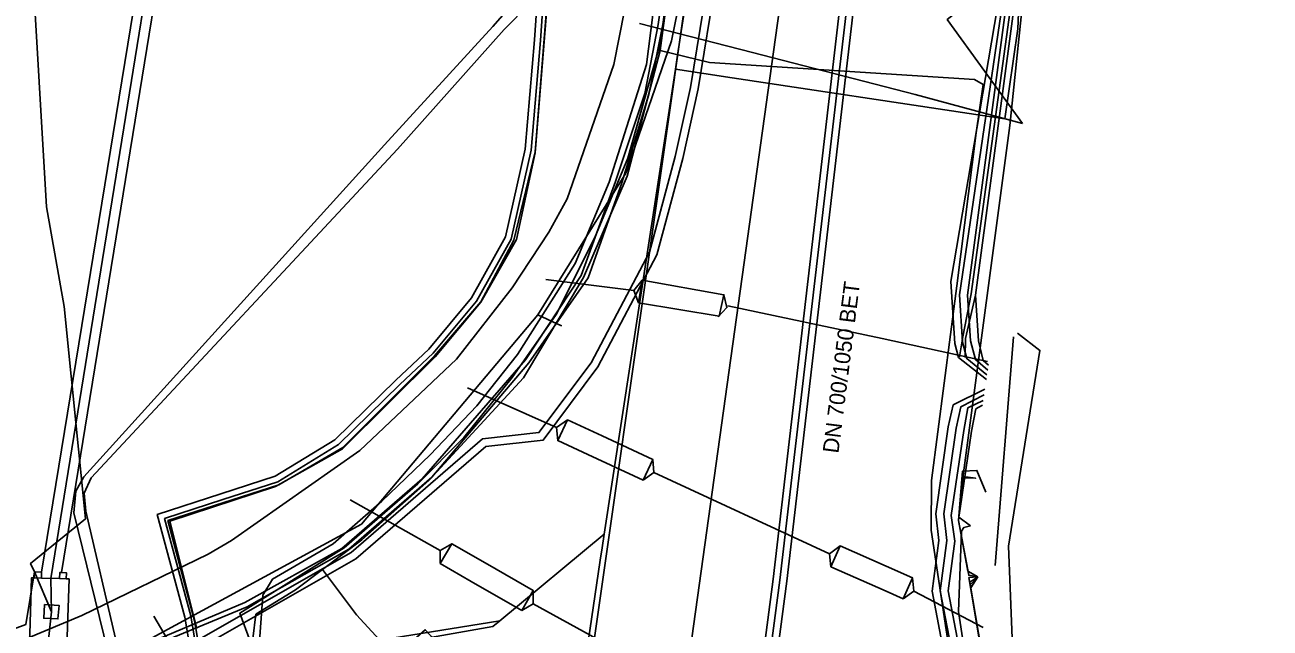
# Model space of a CAD drawing. Extents: x -600309 to -598967, y -1161267 to -1160292.
# Drawn here: x -599138.8 to -599076.1, y -1161098.5 to -1161068.1 of the extents above; entities that cross this region are included whole.
import ezdxf

# ---------------------------------------------------------------- set-up
doc = ezdxf.new("R2010")
doc.units = 0
for name, color, linetype in [('Vrstva 10', 7, 'Continuous'), ('Vrstva 12', 7, 'Continuous'), ('Vrstva 13', 7, 'Continuous'), ('Vrstva 16', 7, 'Continuous'), ('Vrstva 19', 7, 'Continuous'), ('Vrstva 32', 7, 'Continuous'), ('Vrstva 42', 7, 'Continuous'), ('Vrstva 43', 7, 'Continuous'), ('Vrstva 44', 7, 'Continuous'), ('Vrstva 54', 7, 'Continuous'), ('Vrstva 55', 7, 'Continuous'), ('Vrstva 58', 7, 'Continuous'), ('Vrstva 9', 7, 'Continuous')]:
    doc.layers.add(name, color=color, linetype=linetype)

msp = doc.modelspace()

# ---------------------------------------------------------------- linework, layer by layer
at = {"layer": 'Vrstva 10'}
for points in [[(-599137.95, -1161095.67), (-599128.84, -1161039.95)], [(-599136.95, -1161095.7), (-599127.87, -1161039.94)], [(-599100.307, -1161113.292), (-599101.123, -1161110.328), (-599101.597, -1161108.582), (-599101.858, -1161106.427), (-599101.913, -1161103.076), (-599101.585, -1161099.356), (-599101.15, -1161096.037), (-599096.816, -1161058.866)], [(-599096.12, -1161058.948), (-599100.456, -1161096.123), (-599100.889, -1161099.432), (-599101.213, -1161103.101), (-599101.159, -1161106.379), (-599100.908, -1161108.447), (-599100.448, -1161110.144), (-599099.632, -1161113.107)], [(-599138.32, -1161095.96), (-599138.31, -1161095.66), (-599137.95, -1161095.67)], [(-599137.96, -1161095.98), (-599137.95, -1161095.67)], [(-599136.95, -1161095.7), (-599137.04, -1161095.7), (-599137.05, -1161096)], [(-599136.95, -1161095.7), (-599136.7, -1161095.71), (-599136.71, -1161096.01)], [(-599138.32, -1161095.96), (-599138.45, -1161095.96), (-599138.56, -1161099.36), (-599138.4, -1161099.36)], [(-599138.32, -1161095.96), (-599137.96, -1161095.98)], [(-599137.96, -1161095.98), (-599137.05, -1161096)], [(-599137.05, -1161096), (-599136.71, -1161096.01)], [(-599136.71, -1161096.01), (-599136.57, -1161096.02), (-599136.68, -1161099.42), (-599136.83, -1161099.42)], [(-599137.8, -1161097.31), (-599137.07, -1161097.35), (-599137.13, -1161098.03), (-599137.84, -1161098), (-599137.8, -1161097.31)]]:
    msp.add_lwpolyline(points, dxfattribs=at)
at = {"layer": 'Vrstva 12'}
for points in [[(-599137.45, -1161097.68), (-599137.49, -1161095.99), (-599128.41, -1161039.95), (-599127.79, -1161037.74)], [(-599138.17, -1161054.32), (-599138.44, -1161064.71), (-599137.7, -1161077.29), (-599136.81, -1161082.31), (-599135.74, -1161093), (-599138.5, -1161095.24), (-599138.31, -1161095.66)], [(-599089.15, -1161062.53), (-599088.62, -1161063.21), (-599088.83, -1161068.33), (-599089.49, -1161072.87), (-599090.95, -1161072.65), (-599103.21, -1161070.8), (-599106.06, -1161070.37)], [(-599105.24, -1161064.99), (-599105.95, -1161069.66)], [(-599105.95, -1161069.66), (-599106.06, -1161070.37)], [(-599109.65, -1161093.76), (-599106.06, -1161070.37)], [(-599114.89, -1161098.12), (-599109.65, -1161093.76)], [(-599109.75, -1161094.45), (-599109.65, -1161093.76)], [(-599227.66, -1161133.37), (-599206.63, -1161129.68), (-599181.74, -1161125.58), (-599138.25, -1161117.9), (-599112.62, -1161113.97), (-599111.89, -1161109), (-599109.84, -1161095.07), (-599109.75, -1161094.45)], [(-599138.31, -1161095.66), (-599138.74, -1161098.31), (-599144.01, -1161100.25), (-599145.95, -1161101.42), (-599150.35, -1161102.7), (-599150.1, -1161106.59), (-599157.43, -1161107.74), (-599158.7, -1161105.89), (-599162.64, -1161105.89), (-599172.75, -1161107.4), (-599213.54, -1161113.75)], [(-599138.31, -1161095.66), (-599137.45, -1161097.68)], [(-599142.33, -1161117.89), (-599142.31, -1161116.76), (-599137.63, -1161099.39), (-599137.45, -1161097.68)], [(-599134.25, -1161101.76), (-599115.25, -1161098.41), (-599114.89, -1161098.12)], [(-599114.89, -1161098.12), (-599134.06, -1161101.21), (-599134.25, -1161101.76)]]:
    msp.add_lwpolyline(points, dxfattribs=at)
at = {"layer": 'Vrstva 13'}
msp.add_line((-599099.419, -1161057.267), (-599105.229, -1161099.001), dxfattribs=at)
msp.add_lwpolyline([(-599087.218, -1160924.142), (-599087.278, -1160924.842), (-599087.456, -1160926.459), (-599092.039, -1160965.733), (-599102.206, -1161043.368), (-599112.605, -1161116.263), (-599117.926, -1161169.4), (-599117.996, -1161169.89), (-599183.336, -1161201.145), (-599207.239, -1161215.957)], dxfattribs=at)
at = {"layer": 'Vrstva 16'}
for points in [[(-599090.42, -1160990.49), (-599091.72, -1161002.69), (-599092.14, -1161006.66), (-599093.39, -1161018.52), (-599093.73, -1161021.8), (-599093.9, -1161023.39), (-599094.03, -1161024.6), (-599094.38, -1161027.7), (-599097.78, -1161048.16), (-599098.24, -1161050.69), (-599100.21, -1161052.91), (-599108.15, -1161061.44), (-599108.37, -1161061.66), (-599114.17, -1161067.87), (-599114.67, -1161068.37)], [(-599114.67, -1161068.37), (-599120.05, -1161074.39), (-599135.46, -1161090.93), (-599135.8, -1161091.71), (-599135.72, -1161092.6), (-599132.74, -1161105.42), (-599142.28, -1161107.34), (-599150.28, -1161108.75), (-599151.51, -1161109.02), (-599151.83, -1161109.08)]]:
    msp.add_lwpolyline(points, dxfattribs=at)
at = {"layer": 'Vrstva 19'}
for points in [[(-599090.16, -1160981.76), (-599090.66, -1160985.81), (-599091.1, -1160989.88), (-599092.32, -1161001.99), (-599094.19, -1161018.43), (-599094.55, -1161021.61), (-599094.9, -1161024.69), (-599095.21, -1161027.65), (-599098.94, -1161050.34), (-599100.64, -1161052.4), (-599108.52, -1161060.96), (-599114.487, -1161067.355), (-599114.51, -1161067.38), (-599115.24, -1161068.21)], [(-599151.98, -1161108.37), (-599150.36, -1161108.07), (-599146.59, -1161107.5), (-599145.81, -1161107.39), (-599145.43, -1161107.34), (-599142.35, -1161106.87), (-599133.31, -1161105), (-599136.32, -1161092.69), (-599136.23, -1161091.6), (-599135.82, -1161090.88), (-599120.7, -1161074.17), (-599115.24, -1161068.21)]]:
    msp.add_lwpolyline(points, dxfattribs=at)
at = {"layer": 'Vrstva 32'}
msp.add_lwpolyline([(-599127.13, -1161101.25), (-599126.82, -1161096.84), (-599126.34, -1161096.03), (-599123.28, -1161094.25), (-599120.83, -1161092.11), (-599118.4, -1161089.77), (-599116.06, -1161087.31), (-599114.01, -1161084.73), (-599111.11, -1161080.14), (-599109.4, -1161076.05), (-599107.52, -1161070.13), (-599106.87, -1161065.12), (-599106.14, -1161059.09), (-599105.65, -1161058.19), (-599105.52, -1161057.55), (-599104.15, -1161041), (-599104.32, -1161040.43), (-599104.66, -1161039.59), (-599104.74, -1161039.22)], dxfattribs=at)
at = {"layer": 'Vrstva 42'}
msp.add_line((-599123.82, -1161095.544), (-599122.104, -1161097.819), dxfattribs=at)
for points in [[(-599130.144, -1161098.519), (-599130.325, -1161097.797), (-599131.498, -1161093.104), (-599126.174, -1161091.36), (-599122.805, -1161089.465), (-599118.142, -1161084.833), (-599115.856, -1161082.095), (-599114.052, -1161078.937), (-599113.119, -1161074.575), (-599111.254, -1161051.565), (-599110.532, -1161042.661), (-599110.442, -1161037.878), (-599106.953, -1161037.818), (-599100.004, -1161038.299), (-599100.095, -1161032.103), (-599098.651, -1161024.824), (-599097.718, -1161019.921), (-599095.763, -1161007.197)], [(-599100.414, -1161014.387), (-599099.84, -1161014.46), (-599099.73, -1161014.71), (-599100.25, -1161018.35), (-599101.12, -1161026), (-599102.04, -1161032.9), (-599102.92, -1161039.17), (-599103.67, -1161045.42), (-599104.83, -1161053.79), (-599105.874, -1161060.666), (-599106.93, -1161068.11), (-599107.596, -1161071.592), (-599109.08, -1161076.02), (-599110.81, -1161080.75), (-599113.61, -1161084.99), (-599118.81, -1161090.98), (-599122.841, -1161094.49), (-599127.72, -1161097.21), (-599133.25, -1161099.536)], [(-599099.36, -1161013.98), (-599099.393, -1161014.316), (-599099.44, -1161014.8), (-599099.86, -1161018.38), (-599100.88, -1161026.05), (-599101.72, -1161032.93), (-599102.52, -1161039.2), (-599103.38, -1161045.47), (-599104.57, -1161053.82), (-599105.675, -1161060.689), (-599106.69, -1161068.12), (-599107.401, -1161071.642), (-599108.76, -1161076.09), (-599110.45, -1161080.87), (-599113.43, -1161085.14), (-599118.314, -1161090.903), (-599122.494, -1161094.522), (-599127.61, -1161097.43), (-599133.24, -1161099.76)], [(-599130.504, -1161099.33), (-599122.378, -1161094.686), (-599115.768, -1161088.963), (-599112.93, -1161088.652), (-599110.299, -1161085.136), (-599107.371, -1161079.566), (-599106.078, -1161074.758), (-599105.303, -1161071.281), (-599103.531, -1161060.413), (-599102.904, -1161055.233), (-599102.162, -1161048.225), (-599100.926, -1161036.764), (-599100.215, -1161024.999), (-599098.951, -1161019.44), (-599097.017, -1161019.255), (-599084.644, -1161021.242), (-599084.154, -1161021.663), (-599084.081, -1161023.764), (-599084.813, -1161031.922), (-599085.213, -1161036.217), (-599082.49, -1161040.222), (-599078.397, -1161042.629), (-599073.394, -1161041.98)], [(-599130.35, -1161099.703), (-599122.146, -1161095.014), (-599115.6, -1161089.347), (-599112.714, -1161089.031), (-599109.96, -1161085.35), (-599106.996, -1161079.713), (-599105.689, -1161074.853), (-599104.91, -1161071.357), (-599103.135, -1161060.469), (-599102.507, -1161055.278), (-599101.764, -1161048.268), (-599100.527, -1161036.798), (-599099.818, -1161025.056), (-599098.625, -1161019.811), (-599097.03, -1161019.658), (-599084.819, -1161021.619), (-599084.548, -1161021.852), (-599084.482, -1161023.753), (-599085.211, -1161031.886), (-599085.631, -1161036.373), (-599082.813, -1161040.518), (-599078.533, -1161043.05), (-599073.334, -1161042.375)], [(-599090.347, -1161085.515), (-599090.969, -1161084.981), (-599091.213, -1161084.04), (-599091.358, -1161081.729), (-599089.33, -1161066.488), (-599088.744, -1161064.124), (-599085.641, -1161060.959), (-599083.728, -1161060.585), (-599082.593, -1161060.363), (-599082.435, -1161060.333), (-599072.307, -1161058.395), (-599069.64, -1161057.526), (-599069.353, -1161057.433)], [(-599090.308, -1161085.252), (-599090.578, -1161085.018), (-599090.813, -1161084.03), (-599090.956, -1161081.743), (-599088.936, -1161066.563), (-599088.382, -1161064.326), (-599085.442, -1161061.328), (-599082.517, -1161060.756), (-599080.995, -1161060.465), (-599079.644, -1161060.206), (-599072.217, -1161058.785), (-599069.607, -1161057.932), (-599069.293, -1161057.829), (-599069.283, -1161057.826)], [(-599105.36, -1161058.37), (-599106.82, -1161069.43), (-599108.49, -1161075.75), (-599110.68, -1161080.85), (-599113.7, -1161085.89), (-599118.47, -1161091.07), (-599121.84, -1161094.05), (-599123.82, -1161095.544), (-599125.18, -1161096.57), (-599127.17, -1161097.8), (-599127.47, -1161100.28)], [(-599070.03, -1161058.7), (-599077.3, -1161060.1), (-599079.644, -1161060.206), (-599082.435, -1161060.333), (-599085.152, -1161060.456), (-599085.84, -1161060.59), (-599089.106, -1161063.922), (-599089.724, -1161066.413), (-599092.202, -1161081.051)], [(-599069.98, -1161058.99), (-599077.25, -1161060.3), (-599080.995, -1161060.465), (-599083.728, -1161060.585), (-599085.071, -1161060.644), (-599085.74, -1161060.775), (-599088.925, -1161064.023), (-599089.527, -1161066.451), (-599091.76, -1161081.715)], [(-599112.78, -1161063.518), (-599113.15, -1161068.888), (-599113.619, -1161074.387), (-599114.602, -1161078.806), (-599116.314, -1161081.875), (-599118.469, -1161084.447), (-599120.134, -1161086.022), (-599123.203, -1161089.021), (-599126.193, -1161090.853), (-599128.926, -1161091.737), (-599132.128, -1161092.782), (-599130.737, -1161097.942), (-599130.056, -1161102.037)], [(-599112.78, -1161063.518), (-599113.15, -1161068.888), (-599113.619, -1161074.387), (-599114.602, -1161078.806), (-599116.314, -1161081.875), (-599118.469, -1161084.447), (-599120.134, -1161086.022), (-599123.203, -1161089.021), (-599126.193, -1161090.853), (-599128.926, -1161091.737), (-599132.128, -1161092.782), (-599130.737, -1161097.942), (-599130.056, -1161102.037)], [(-599130.056, -1161102.037), (-599130.737, -1161097.942), (-599132.128, -1161092.782), (-599128.926, -1161091.737), (-599126.193, -1161090.853), (-599123.203, -1161089.021), (-599120.134, -1161086.022), (-599118.469, -1161084.447), (-599116.314, -1161081.875), (-599114.602, -1161078.806), (-599113.619, -1161074.387), (-599113.15, -1161068.888), (-599112.78, -1161063.518)], [(-599130.056, -1161102.037), (-599130.737, -1161097.942), (-599132.128, -1161092.782), (-599128.926, -1161091.737), (-599126.193, -1161090.853), (-599123.203, -1161089.021), (-599120.134, -1161086.022), (-599118.469, -1161084.447), (-599116.314, -1161081.875), (-599114.602, -1161078.806), (-599113.619, -1161074.387), (-599113.15, -1161068.888), (-599112.78, -1161063.518)], [(-599112.48, -1161063.542), (-599112.85, -1161068.912), (-599113.321, -1161074.433), (-599114.318, -1161078.914), (-599116.066, -1161082.045), (-599118.251, -1161084.653), (-599119.926, -1161086.238), (-599123.017, -1161089.259), (-599126.067, -1161091.127), (-599128.834, -1161092.023), (-599131.764, -1161092.978), (-599130.443, -1161097.878), (-599129.764, -1161101.963)], [(-599112.48, -1161063.542), (-599112.85, -1161068.912), (-599113.321, -1161074.433), (-599114.318, -1161078.914), (-599116.066, -1161082.045), (-599118.251, -1161084.653), (-599119.926, -1161086.238), (-599123.017, -1161089.259), (-599126.067, -1161091.127), (-599128.834, -1161092.023), (-599131.764, -1161092.978), (-599130.443, -1161097.878), (-599129.764, -1161101.963)], [(-599129.764, -1161101.963), (-599130.443, -1161097.878), (-599131.764, -1161092.978), (-599128.834, -1161092.023), (-599126.067, -1161091.127), (-599123.017, -1161089.259), (-599119.926, -1161086.238), (-599118.251, -1161084.653), (-599116.066, -1161082.045), (-599114.318, -1161078.914), (-599113.321, -1161074.433), (-599112.85, -1161068.912), (-599112.48, -1161063.542)], [(-599129.764, -1161101.963), (-599130.443, -1161097.878), (-599131.764, -1161092.978), (-599128.834, -1161092.023), (-599126.067, -1161091.127), (-599123.017, -1161089.259), (-599119.926, -1161086.238), (-599118.251, -1161084.653), (-599116.066, -1161082.045), (-599114.318, -1161078.914), (-599113.321, -1161074.433), (-599112.85, -1161068.912), (-599112.48, -1161063.542)], [(-599106.82, -1161069.43), (-599104.34, -1161070.02), (-599091.02, -1161070.89), (-599090.58, -1161071.13), (-599090.93, -1161073.57), (-599091.9, -1161081.27), (-599093.17, -1161091.06), (-599093.2, -1161093.56), (-599091.91, -1161102.04), (-599090.53, -1161110.56), (-599089.55, -1161114.3), (-599089.54, -1161115.36), (-599089.44, -1161117.31), (-599087.64, -1161128.65), (-599086.47, -1161136.043), (-599086.45, -1161136.17)], [(-599090.415, -1161085.979), (-599091.824, -1161084.869), (-599092.007, -1161084.166), (-599092.202, -1161081.051)], [(-599090.387, -1161085.747), (-599091.395, -1161084.929), (-599091.61, -1161084.103), (-599091.76, -1161081.715)], [(-599089.951, -1161101.884), (-599091.147, -1161102.085), (-599091.364, -1161102.122), (-599091.758, -1161102.188), (-599092.163, -1161102.256), (-599092.519, -1161099.912), (-599093.143, -1161096.634), (-599092.806, -1161094.079), (-599092.957, -1161092.735), (-599092.333, -1161088.361), (-599092.087, -1161087.264), (-599090.486, -1161086.46)], [(-599092.125, -1161099.844), (-599092.738, -1161096.622), (-599092.403, -1161094.083), (-599092.554, -1161092.741), (-599091.939, -1161088.433), (-599091.697, -1161087.351), (-599090.529, -1161086.755)], [(-599091.731, -1161099.776), (-599092.333, -1161096.611), (-599092.005, -1161094.126), (-599092.182, -1161092.834), (-599091.548, -1161088.545), (-599091.343, -1161087.407), (-599090.579, -1161087.034)], [(-599091.22, -1161093.349), (-599091.809, -1161092.909), (-599091.734, -1161092.48), (-599091.156, -1161088.582), (-599090.951, -1161087.463), (-599090.606, -1161087.267)], [(-599075.53, -1161170.56), (-599076.33, -1161169.081), (-599081.234, -1161152.226), (-599081.4, -1161151.64), (-599082.1, -1161149.27), (-599082.835, -1161148.246), (-599084.244, -1161144.807), (-599084.46, -1161143.85), (-599085.49, -1161135.84), (-599086.55, -1161126.97), (-599088.14, -1161117.83), (-599089.18, -1161110.51), (-599090.437, -1161106.747), (-599091.147, -1161102.085), (-599091.82, -1161097.66), (-599091.67, -1161093.62), (-599091.543, -1161093.428), (-599091.22, -1161093.349)], [(-599122.104, -1161097.819), (-599120.177, -1161099.922), (-599117.79, -1161102.364), (-599116.247, -1161101.122), (-599118.649, -1161098.58), (-599120.177, -1161099.922)]]:
    msp.add_lwpolyline(points, dxfattribs=at)
at = {"layer": 'Vrstva 43'}
for points in [[(-599104.705, -1161038.886), (-599104.385, -1161039.007), (-599104.578, -1161042.508), (-599104.348, -1161042.993), (-599105.017, -1161048.849), (-599104.688, -1161049.187), (-599105.212, -1161053.262), (-599104.743, -1161053.77), (-599105.578, -1161059.006), (-599105.607, -1161059.745), (-599106.77, -1161068.9), (-599108.455, -1161074.846), (-599110.111, -1161078.833), (-599112.055, -1161082.703), (-599114.272, -1161085.889), (-599116.7, -1161088.9), (-599119.028, -1161091.234), (-599122.728, -1161094.447), (-599127.974, -1161097.737), (-599127.455, -1161099.145)], [(-599127.641, -1161100.906), (-599127.455, -1161099.145), (-599127.974, -1161097.737), (-599122.728, -1161094.447), (-599119.028, -1161091.234), (-599116.7, -1161088.9), (-599114.272, -1161085.889), (-599112.055, -1161082.703), (-599110.111, -1161078.833), (-599108.455, -1161074.846), (-599106.77, -1161068.9), (-599105.607, -1161059.745)], [(-599127.641, -1161100.906), (-599127.455, -1161099.145), (-599127.974, -1161097.737), (-599122.728, -1161094.447), (-599119.028, -1161091.234), (-599116.7, -1161088.9), (-599114.272, -1161085.889), (-599112.055, -1161082.703), (-599110.111, -1161078.833), (-599108.455, -1161074.846), (-599106.77, -1161068.9), (-599105.607, -1161059.745)]]:
    msp.add_lwpolyline(points, dxfattribs=at)
at = {"layer": 'Vrstva 44'}
for points in [[(-599130.504, -1161099.33), (-599122.378, -1161094.686), (-599115.768, -1161088.963), (-599112.93, -1161088.652), (-599110.299, -1161085.136), (-599107.371, -1161079.566), (-599106.078, -1161074.758), (-599105.303, -1161071.281), (-599103.531, -1161060.413), (-599102.904, -1161055.233), (-599102.162, -1161048.225), (-599100.926, -1161036.764), (-599101.244, -1161035.063), (-599100.215, -1161024.999), (-599098.951, -1161019.44), (-599097.017, -1161019.255), (-599084.644, -1161021.242), (-599083.85, -1161021.784), (-599083.804, -1161023.796), (-599083.804, -1161023.796)], [(-599091.489, -1161084.874), (-599091.46, -1161083.922), (-599090.956, -1161081.743), (-599088.936, -1161066.563), (-599088.382, -1161064.326), (-599085.442, -1161061.328), (-599082.517, -1161060.756), (-599072.217, -1161058.785)], [(-599076.726, -1161059.5), (-599082.467, -1161060.531), (-599085.573, -1161061.078), (-599088.677, -1161064.464), (-599089.101, -1161066.522), (-599091.175, -1161081.674), (-599091.598, -1161083.827), (-599091.775, -1161084.837)]]:
    msp.add_lwpolyline(points, dxfattribs=at)
at = {"layer": 'Vrstva 54'}
for points in [[(-599087.782, -1161064.259), (-599092.38, -1161067.87), (-599088.595, -1161073.096)], [(-599107.87, -1161068.06), (-599102.19, -1161069.53)], [(-599102.19, -1161069.53), (-599093.99, -1161071.64), (-599088.595, -1161073.096)], [(-599108.16, -1161081.5), (-599112.58, -1161080.95)], [(-599107.926, -1161082.124), (-599107.738, -1161080.984), (-599108.16, -1161081.5), (-599107.926, -1161082.124)], [(-599107.738, -1161080.984), (-599103.622, -1161081.716)], [(-599103.907, -1161082.832), (-599103.466, -1161082.364), (-599103.622, -1161081.716), (-599103.852, -1161082.796)], [(-599103.852, -1161082.796), (-599107.926, -1161082.124)], [(-599103.43, -1161082.28), (-599095.65, -1161083.92), (-599090.351, -1161085.081)], [(-599116.52, -1161086.4), (-599112.04, -1161088.39)], [(-599111.495, -1161088.006), (-599111.983, -1161089.054), (-599112.04, -1161088.39), (-599111.495, -1161088.006)], [(-599111.495, -1161088.006), (-599109.74, -1161088.82), (-599107.197, -1161090.006)], [(-599107.685, -1161091.054), (-599110.46, -1161089.76), (-599111.983, -1161089.054)], [(-599107.685, -1161091.054), (-599107.14, -1161090.67), (-599107.197, -1161090.006), (-599107.685, -1161091.054)], [(-599107.14, -1161090.67), (-599098.31, -1161094.75)], [(-599117.89, -1161094.58), (-599122.43, -1161092.03)], [(-599117.89, -1161095.247), (-599117.314, -1161094.244), (-599117.89, -1161094.58), (-599117.89, -1161095.247)], [(-599117.314, -1161094.244), (-599115.51, -1161095.28), (-599113.21, -1161096.603)], [(-599098.24, -1161095.413), (-599097.773, -1161094.356), (-599098.31, -1161094.75), (-599098.24, -1161095.413)], [(-599094.13, -1161095.967), (-599095.46, -1161095.38), (-599097.773, -1161094.356)], [(-599113.786, -1161097.606), (-599116.34, -1161096.14), (-599117.89, -1161095.247)], [(-599098.24, -1161095.413), (-599095.46, -1161096.64), (-599094.597, -1161097.024)], [(-599094.597, -1161097.024), (-599094.06, -1161096.63), (-599094.13, -1161095.967), (-599094.597, -1161097.024)], [(-599113.786, -1161097.606), (-599113.21, -1161097.27), (-599113.21, -1161096.603), (-599113.786, -1161097.606)], [(-599094.06, -1161096.63), (-599090.585, -1161098.467)], [(-599113.21, -1161097.27), (-599093.99, -1161107.84), (-599088.676, -1161111.038)], [(-599132.3, -1161097.9), (-599129.745, -1161102.255)]]:
    msp.add_lwpolyline(points, dxfattribs=at)
at = {"layer": 'Vrstva 55'}
for points in [[(-599090.84, -1161095.91), (-599091.3, -1161095.83), (-599091.81, -1161093.07), (-599091.583, -1161090.856), (-599090.956, -1161090.955), (-599091.599, -1161090.939), (-599089.24, -1161073.19), (-599088.41, -1161065.29), (-599087.626, -1161065.418), (-599088.41, -1161065.25), (-599088.1, -1161063.38), (-599085.36, -1161060.48), (-599084.37, -1161060.16), (-599075.9, -1161058.81), (-599076.05, -1161057.55), (-599076.03, -1161058.78), (-599071.62, -1161058.23), (-599067.97, -1161057.84), (-599067.7, -1161059.37), (-599067.25, -1161059.29)], [(-599141.44, -1161099.07), (-599142.05, -1161098.7), (-599144.93, -1161099.4), (-599143.7, -1161103.65), (-599139.21, -1161102.77), (-599138.9, -1161103.72), (-599139.21, -1161102.69), (-599121.86, -1161093.26), (-599112.99, -1161082.72), (-599111.8, -1161083.28), (-599112.99, -1161082.72), (-599108.55, -1161075.59), (-599106.25, -1161068.94), (-599104.98, -1161062.68), (-599103.89, -1161062.52)], [(-599088.845, -1161083.655), (-599087.72, -1161084.515), (-599089.308, -1161094.371), (-599088.333, -1161118.754), (-599101.505, -1161119.752), (-599108.266, -1161118.754), (-599126.65, -1161121.657), (-599215.474, -1161136.17), (-599215.117, -1161138.589)], [(-599089.054, -1161083.838), (-599089.98, -1161095.348)], [(-599090.45, -1161091.66), (-599090.89, -1161090.56), (-599091.62, -1161090.6), (-599091.81, -1161093.07), (-599091.35, -1161095.62), (-599090.84, -1161095.91)], [(-599090.84, -1161095.91), (-599091.23, -1161096.31), (-599087.57, -1161118.29), (-599101.47, -1161119.87), (-599106.18, -1161119.07), (-599108.28, -1161119.03), (-599117.23, -1161120), (-599116.83, -1161108.93), (-599117.25, -1161119.79), (-599139.3, -1161123.44), (-599139.85, -1161120.7), (-599139.38, -1161123.41), (-599174.24, -1161129.25), (-599174.73, -1161126.37), (-599174.32, -1161129.28), (-599203.685, -1161134.434), (-599204.06, -1161131.51)], [(-599090.84, -1161095.91), (-599091.19, -1161096.46), (-599085.6, -1161130.6), (-599089.89, -1161130.36), (-599095.07, -1161129.87), (-599108.77, -1161128.97), (-599109.79, -1161133.07), (-599110.065, -1161137.802), (-599115.78, -1161152.62), (-599120.426, -1161159.167), (-599127.414, -1161166.476), (-599132.16, -1161170.12)], [(-599090.84, -1161095.91), (-599091.29, -1161095.95), (-599087.5, -1161118.19)], [(-599090.84, -1161095.91), (-599091.24, -1161096.18), (-599087.5, -1161118.19), (-599087.058, -1161118.207), (-599087.46, -1161118.22), (-599084.74, -1161137.86), (-599083.5, -1161145.58), (-599082.801, -1161145.095), (-599083.45, -1161145.47), (-599078.7, -1161148.45), (-599072.64, -1161147.58)]]:
    msp.add_lwpolyline(points, dxfattribs=at)
at = {"layer": 'Vrstva 58'}
for points in [[(-599137.63, -1161099.39), (-599137.45, -1161097.68), (-599137.49, -1161095.99), (-599128.41, -1161039.95), (-599127.79, -1161037.74), (-599124.7, -1161037.73), (-599107.92, -1161035.05), (-599105.89, -1161034.84), (-599103.9, -1161034.82), (-599087.5, -1161033.66), (-599086.86, -1161033.06), (-599078.59, -1160971.02)], [(-599137.63, -1161099.39), (-599137.45, -1161097.68), (-599137.49, -1161095.99), (-599128.41, -1161039.95), (-599127.79, -1161037.74), (-599124.7, -1161037.73), (-599107.92, -1161035.05), (-599105.89, -1161034.84), (-599103.9, -1161034.82), (-599087.5, -1161033.66), (-599086.86, -1161033.06), (-599078.59, -1160971.02)], [(-599137.63, -1161099.39), (-599137.45, -1161097.68), (-599137.49, -1161095.99), (-599128.41, -1161039.95), (-599127.79, -1161037.74), (-599124.7, -1161037.73), (-599107.92, -1161035.05), (-599105.89, -1161034.84), (-599103.9, -1161034.82), (-599087.5, -1161033.66), (-599086.86, -1161033.06), (-599078.59, -1160971.02)], [(-599096.159, -1161010.297), (-599097.954, -1161020.94), (-599100.074, -1161032.032), (-599099.952, -1161038.23), (-599107.088, -1161037.863), (-599110.513, -1161037.944), (-599110.472, -1161042.675), (-599111.288, -1161051.564), (-599113.123, -1161074.522), (-599114.183, -1161078.966), (-599115.855, -1161082.065), (-599118.179, -1161084.797), (-599122.787, -1161089.405), (-599126.008, -1161091.281), (-599131.595, -1161093.075), (-599130.249, -1161098.132), (-599129.597, -1161101.883)], [(-599102.08, -1161032.02), (-599103.28, -1161040.84), (-599103.99, -1161041.64), (-599105.53, -1161042.7), (-599105.74, -1161044.08), (-599107.2, -1161057.69), (-599107.66, -1161060.45), (-599107.673, -1161060.68), (-599108.35, -1161066.03), (-599109.167, -1161070.123), (-599111.5, -1161076.89), (-599112.43, -1161078.56), (-599114.28, -1161081.37), (-599117.08, -1161084.95), (-599121.94, -1161089.56), (-599128.39, -1161094.08), (-599129.57, -1161094.78), (-599135.93, -1161097.86), (-599139.61, -1161099.41)]]:
    msp.add_lwpolyline(points, dxfattribs=at)
at = {"layer": 'Vrstva 9'}
msp.add_lwpolyline([(-599096.468, -1161058.907), (-599100.803, -1161096.08), (-599101.237, -1161099.394), (-599101.563, -1161103.089), (-599101.509, -1161106.403), (-599101.252, -1161108.515), (-599100.785, -1161110.236), (-599099.97, -1161113.199)], dxfattribs=at)

# ---------------------------------------------------------------- texts
at = {"layer": 'Vrstva 12'}
msp.add_text('DN 700/1050 BET', height=0.8, rotation=82.79662, dxfattribs=at).set_placement((-599097.861, -1161089.725))

doc.saveas('drawing.dxf')
